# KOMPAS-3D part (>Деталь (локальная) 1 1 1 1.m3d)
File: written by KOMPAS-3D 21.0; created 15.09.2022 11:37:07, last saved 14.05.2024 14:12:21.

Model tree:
1. Эскиз:1

Referenced files in C:\Program Files\Ascon\Libs\EasySteel\: Rolled metal.kle, StandartSolutions.kle, DSTVProperties.lpt
Referenced files in W:\Шаблоны чертежей\: Констр. чертеж А3 гориз. перв. лист.cdt
Referenced files in C:\Program Files\Ascon\Libs\EasySteel\BeltEndings\: 
Referenced files in C:\Program Files\Ascon\Libs\EasySteel\Punctures\: 
Referenced files in C:\Program Files\Ascon\Libs\EasySteel\Insulations\: 
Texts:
  Уголок равнополочный по ГОСТ 8509-93 (Спец)
  config2DpacketName
  config2DstdSizeID
  Констр. чертеж А3 гориз. перв. лист.cdt
  Болт ГОСТ 22353-77
  Шайба ГОСТ 22355-77
  Гайка ГОСТ 22354-77
  Нормальная пружинная шайба ГОСТ 6402-70 (исп. 1)
  SeaRox SL 436
  Сталь 09Г2С ГОСТ 19281-2014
